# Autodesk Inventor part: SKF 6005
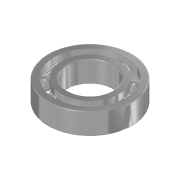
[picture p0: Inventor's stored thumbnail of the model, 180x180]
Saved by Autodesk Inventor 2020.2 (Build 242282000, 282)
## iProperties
Manager: www.cadconsulting.pl
Company: Fabian Stasiak CAD Consulting
+MSCProtocol1+ProtocolID: P00060228133459765
+MSCProtocol2+Protocol: P00060228133459765<@PID>[Version]<@EL>Version=2.2<@EL>[Files]<@EL>DataFile=SpiData|n024630a<@EL>[Synchronize]<@EL>ChangedVars=<@EL>[Calc]<@EL>DDmin=<@EL>DDmax=<
Shininess: 20.0
Length Units: 11269
Angle Units: 11279
Time Units: 11290
Mass Units: 11283
Length Display Precision: 3
Angle Display Precision: 2
Created: 2001-01
Part Number: SKF 6005
Material: Stal
Document SubType Name: Modeling
Description: Łożysko SKF 6005
Stock Number: SKF 6005
Project: Przekładnia X51
Designer: F.Stasiak
Density: 7.85 g/cm^3
Appearance: Chrom
Density: 7.86
Volumn: 47.63899704516156
Area: 199.2492810037185
PropertySet Name: Model Information
Control State: 0
Master: False
Checked Out: False
BOM1: Łożysko
BOM2: SKF 6005
Author: F.Stasiak
Subject: Zbiór ćwiczeń. Autodesk Inventor 2020. Kurs podstawowy
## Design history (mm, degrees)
node "Sketch1"
node "WorkPoint1"
sketch "Sketch2"
  geometry: L1 (12.5, 12)-(23.5, 12); L2 (12.5, 0)-(12.5, 12); L3 (23.5, 0)-(12.5, 0); L4 (23.5, 12)-(23.5, 0); L5 (0, 0)-(0, 20); L6 (0, 0)-(0, 20); L7 (-3.6, 0)-(46.8, 0) reference
  constraints: 12 end point, 3 vertical, 2 horizontal, 1 collinear, 1 other
  dimensions: "d1" = 25 diameter of L1.start L5 (= prf_d); "d3" = 47 diameter of L1.end L5 (= prf_dd); "d5" = 12 distance of L2.start L1.start (= msp_mdtd2)
revolve "RevolutionFull1" sketch "Sketch2" stored, may be unused: angle "d6" = 360 deg
node "WorkAxis1"
node "WorkPlane3"
sketch "Sketch3"
  geometry: L1 (19.98, 12)-(19.98, 8.64); L2 (16.02, 12)-(19.98, 12); L3 (16.02, 8.64)-(16.02, 12); L4 (16.02, 0)-(16.02, 3.36); L5 (19.98, 0)-(16.02, 0); L6 (19.98, 3.36)-(19.98, 0); L7 (23.5, 0)-(-23.5, 0) reference; L8 (23.5, 12)-(-23.5, 12) reference; L9 (0, -42.29)-(0, 61.29); L10 (0, 92.365)-(0, -52.649) reference; A1 r 3.3 centre (18, 6) between (19.98, 3.36) and (19.98, 8.64); A2 r 3.3 centre (18, 6) between (16.02, 8.64) and (16.02, 3.36)
  constraints: 14 end point, 4 collinear, 4 point on circle, 4 vertical, 2 centre point, 2 concentric, 2 horizontal, 2 point on line
  dimensions: "d9" = 6.6 diameter of A1 (= msp_mdtd6); "d21" = 16.02 distance between parallel lines of L9 L4 (= 0.5 x msp_d1); "d22" = 18 distance from line of L9 A1.centre (= 0.5 x msp_ds); "d23" = 19.98 distance between parallel lines of L9 L6 (= 0.5 x msp_dd1)
revolve "RevolutionFull2" sketch "Sketch3" stored, may be unused: angle "d10" = 360 deg
node "WorkPlane4"
node "Sketch4"
node "WorkPoint2"
revolve "RevolutionFull3" stored, may be unused: angle "d16" = 360 deg
pattern_circular "PolarAray1" dims "d17" = 85.81818 (= msp_pocet), angle "d19" = 360 deg
fillet "Fillet1" dims "d20" = 0.6 (= prf_r)
node "Bryła1"
node "Korpusy bryłowe"
node "Korpusy powierzchniowe"
sketch "Sketch5"
  geometry: L1 (18, 2.7)-(18, 9.3); L2 (19.98, 0)-(-19.98, 0) reference; L3 (18, 2.7)-(18, 9.3); A1 r 3.3 centre (18, 6) between (18, 2.7) and (18, 9.3); A2 r 3.3 centre (18, 6) between (19.98, 3.36) and (19.98, 8.64) reference
  constraints: 4 end point, 2 point on circle, 1 centre point, 1 concentric, 1 vertical
  dimensions: "d13" = 0 horizontal distance of A1.centre L1.start; "d15" = 6.6001 diameter of A1 (computed from msp_mdtd6)
other parameters: "prf_d" = 25 [user parameter; used in 3 equation terms], "prf_dd" = 47 [user parameter; used in 3 equation terms], "prf_b" = 12 [user parameter; used in 1 equation term], "prf_r" = 0.6 [user parameter; used in 1 equation term], "msp_ds" = 36 (= 0.5 x prf_d + 0.5 x prf_dd) [user parameter; used in 5 equation terms], "msp_d0" = 6.6 (= -0.3 x prf_d + 0.3 x prf_dd) [user parameter; used in 4 equation terms], "msp_d1" = 32.04 (= msp_ds - 0.6 x msp_d0) [user parameter; used in 1 equation term], "msp_dd1" = 39.96 (= msp_ds + 0.6 x msp_d0) [user parameter; used in 1 equation term], "msp_pom" = 54 (= 1.5 x msp_ds) [user parameter; used in 1 equation term], "msp_mdtd2" = 12 (= prf_b) [user parameter; used in 3 equation terms], "msp_mdtd4" = 36 (= msp_ds) [user parameter], "msp_mdtd6" = 6.6 (= msp_d0) [user parameter; used in 2 equation terms], "msp_mdtd7" = 6 (= 0.5 x msp_mdtd2) [user parameter], "msp_pocet" = 85.81818 (computed from msp_d0, msp_pom) [user parameter; used in 1 equation term], "d2" = 72 (derived), "d4" = 19 (derived), "d7" = 0, "d8" = 15.6 (derived), "d11" = -12 (computed from msp_mdtd2), "d12" = 0 (derived), "d14" = 15.6001 (derived), "d25" = 0
